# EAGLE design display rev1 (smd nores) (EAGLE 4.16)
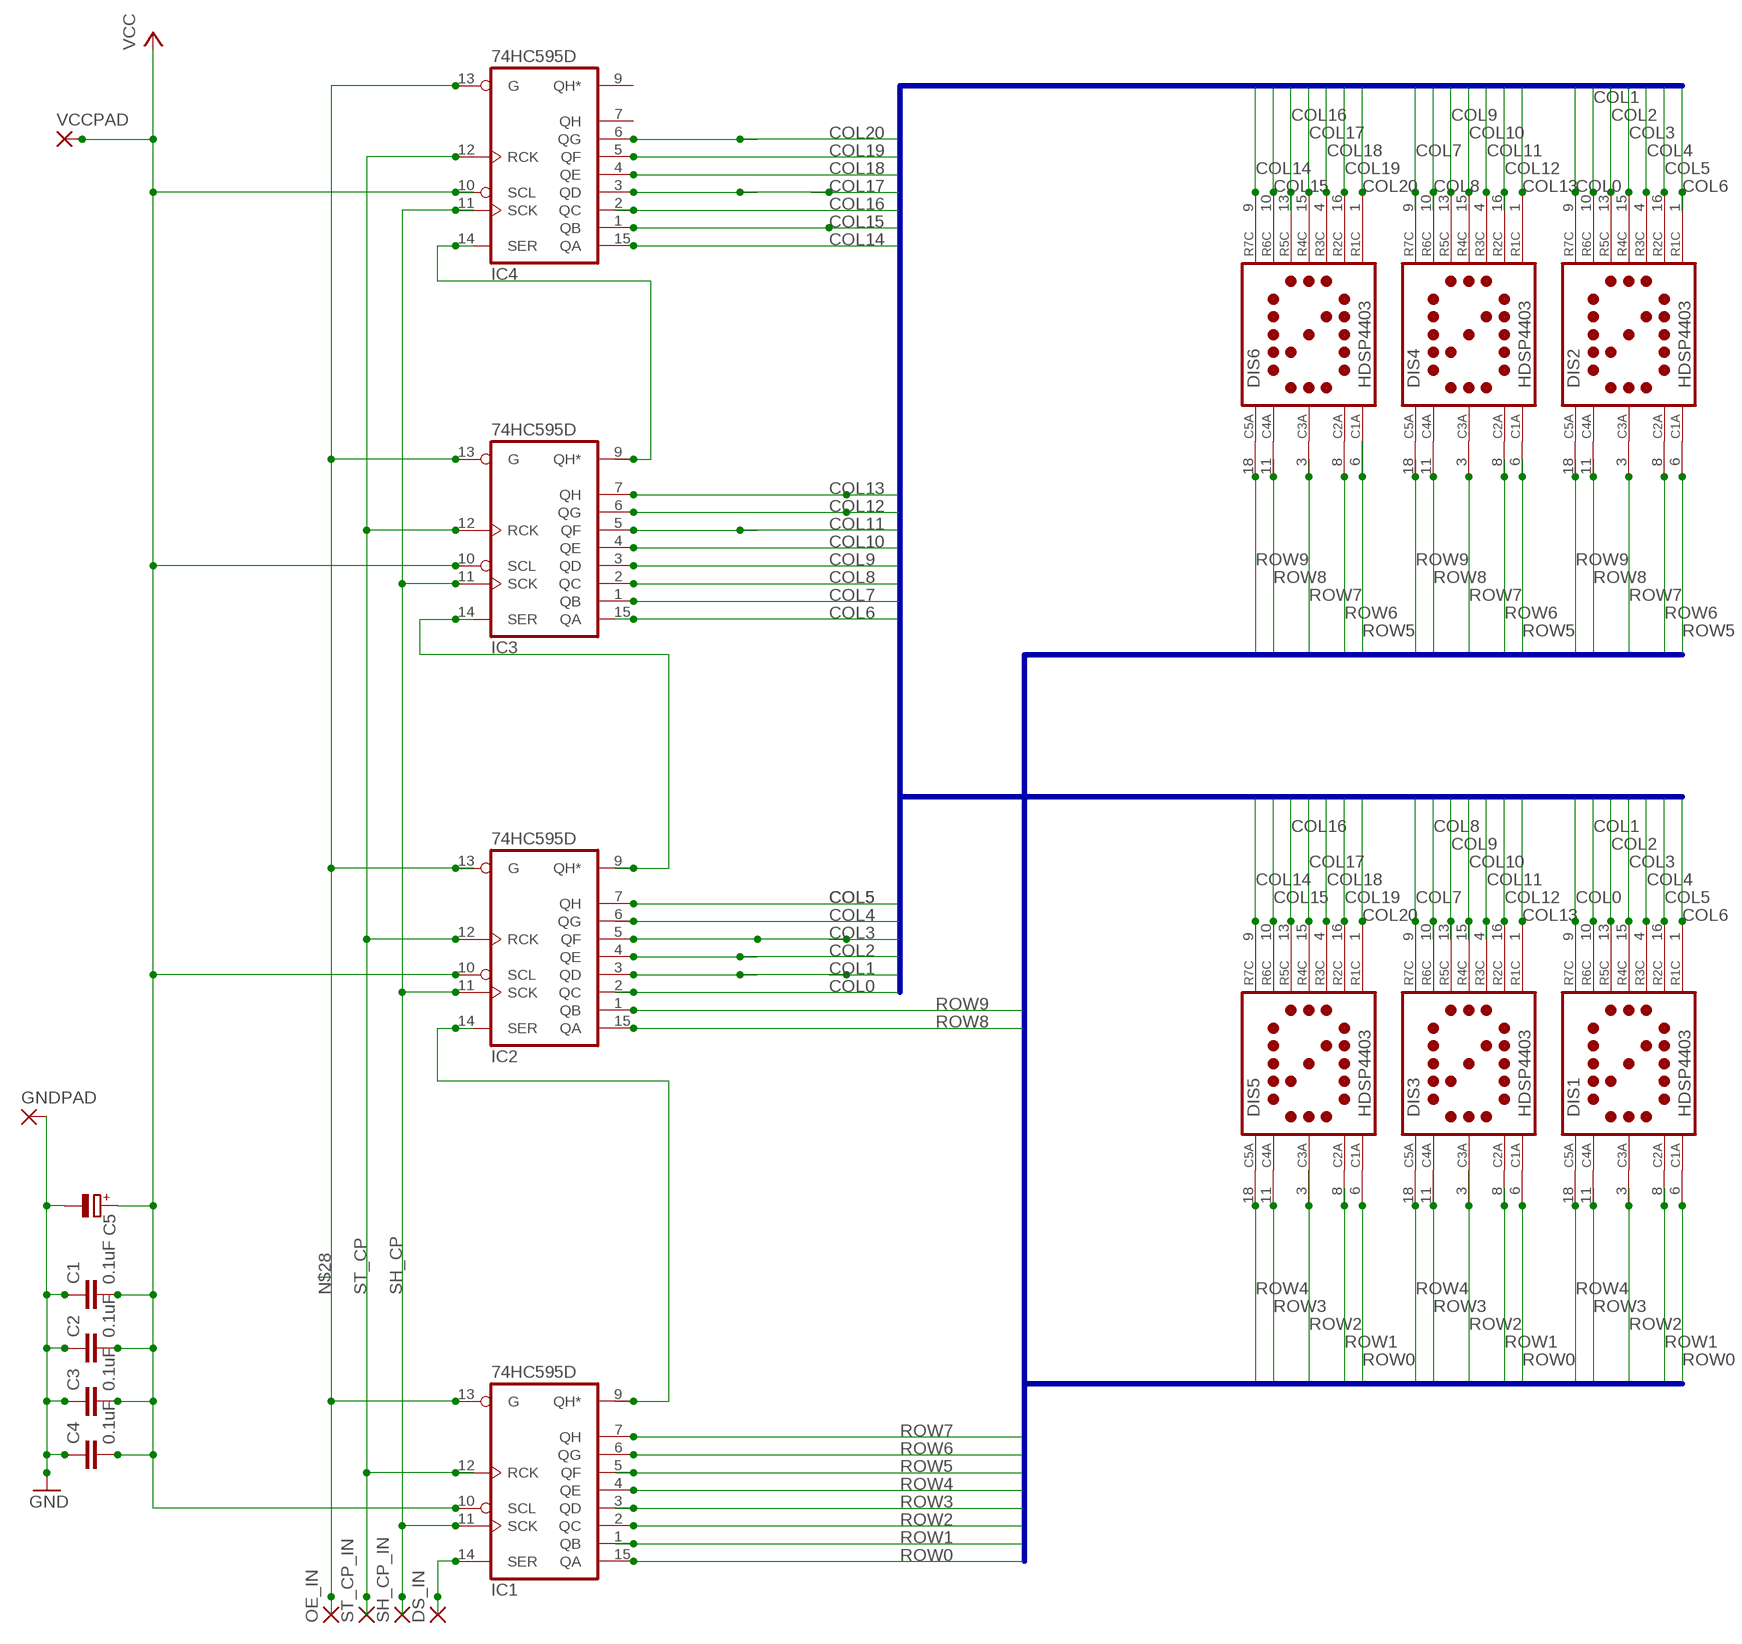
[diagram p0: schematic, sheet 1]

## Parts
C1  0.1uF  C-EUC0805K  [C0805K]
C2  0.1uF  C-EUC0805K  [C0805K]
C3  0.1uF  C-EUC0805K  [C0805K]
C4  0.1uF  C-EUC0805K  [C0805K]
C5  CPOL-EUA/3216-18W  [A/3216-18W]
DIS1  HDSP4403  [HDSP44]
DIS2  HDSP4403  [HDSP44]
DIS3  HDSP4403  [HDSP44]
DIS4  HDSP4403  [HDSP44]
DIS5  HDSP4403  [HDSP44]
DIS6  HDSP4403  [HDSP44]
DS_IN  2,15/1,0  [2,15/1,0]
GNDPAD  2,15/1,0  [2,15/1,0]
IC1  74HC595D  [SO16]
IC2  74HC595D  [SO16]
IC3  74HC595D  [SO16]
IC4  74HC595D  [SO16]
OE_IN  2,15/1,0  [2,15/1,0]
SH_CP_IN  2,15/1,0  [2,15/1,0]
ST_CP_IN  2,15/1,0  [2,15/1,0]
VCCPAD  2,15/1,0  [2,15/1,0]

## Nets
COL0: DIS1.9(R7C) DIS2.9(R7C) IC2.2(QC)
COL1: DIS1.10(R6C) DIS2.10(R6C) IC2.3(QD)
COL2: DIS1.13(R5C) DIS2.13(R5C) IC2.4(QE)
COL3: DIS1.15(R4C) DIS2.15(R4C) IC2.5(QF)
COL4: DIS1.4(R3C) DIS2.4(R3C) IC2.6(QG)
COL5: DIS1.16(R2C) DIS2.16(R2C) IC2.7(QH)
COL6: DIS1.1(R1C) DIS2.1(R1C) IC3.15(QA)
COL7: DIS3.9(R7C) DIS4.9(R7C) IC3.1(QB)
COL8: DIS3.10(R6C) DIS4.10(R6C) IC3.2(QC)
COL9: DIS3.13(R5C) DIS4.13(R5C) IC3.3(QD)
COL10: DIS3.15(R4C) DIS4.15(R4C) IC3.4(QE)
COL11: DIS3.4(R3C) DIS4.4(R3C) IC3.5(QF)
COL12: DIS3.16(R2C) DIS4.16(R2C) IC3.6(QG)
COL13: DIS3.1(R1C) DIS4.1(R1C) IC3.7(QH)
COL14: DIS5.9(R7C) DIS6.9(R7C) IC4.15(QA)
COL15: DIS5.10(R6C) DIS6.10(R6C) IC4.1(QB)
COL16: DIS5.13(R5C) DIS6.13(R5C) IC4.2(QC)
COL17: DIS5.15(R4C) DIS6.15(R4C) IC4.3(QD)
COL18: DIS5.4(R3C) DIS6.4(R3C) IC4.4(QE)
COL19: DIS5.16(R2C) DIS6.16(R2C) IC4.5(QF)
COL20: DIS5.1(R1C) DIS6.1(R1C) IC4.6(QG)
GND: C1.1 C2.1 C3.1 C4.1 C5.- GNDPAD.1(P)
N$22: IC1.9(QH*) IC2.14(SER)
N$23: IC2.9(QH*) IC3.14(SER)
N$24: IC3.9(QH*) IC4.14(SER)
N$28: IC1.13(G) IC2.13(G) IC3.13(G) IC4.13(G) OE_IN.1(P)
N$29: DS_IN.1(P) IC1.14(SER)
ROW0: DIS1.6(C1A) DIS3.6(C1A) DIS5.6(C1A) IC1.15(QA)
ROW1: DIS1.8(C2A) DIS3.8(C2A) DIS5.8(C2A) IC1.1(QB)
ROW2: DIS1.3(C3A) DIS3.3(C3A) DIS5.3(C3A) IC1.2(QC)
ROW3: DIS1.11(C4A) DIS3.11(C4A) DIS5.11(C4A) IC1.3(QD)
ROW4: DIS1.18(C5A) DIS3.18(C5A) DIS5.18(C5A) IC1.4(QE)
ROW5: DIS2.6(C1A) DIS4.6(C1A) DIS6.6(C1A) IC1.5(QF)
ROW6: DIS2.8(C2A) DIS4.8(C2A) DIS6.8(C2A) IC1.6(QG)
ROW7: DIS2.3(C3A) DIS4.3(C3A) DIS6.3(C3A) IC1.7(QH)
ROW8: DIS2.11(C4A) DIS4.11(C4A) DIS6.11(C4A) IC2.15(QA)
ROW9: DIS2.18(C5A) DIS4.18(C5A) DIS6.18(C5A) IC2.1(QB)
SH_CP: IC1.11(SCK) IC2.11(SCK) IC3.11(SCK) IC4.11(SCK) SH_CP_IN.1(P)
ST_CP: IC1.12(RCK) IC2.12(RCK) IC3.12(RCK) IC4.12(RCK) ST_CP_IN.1(P)
VCC: C1.2 C2.2 C3.2 C4.2 C5.+ IC1.10(SCL) IC2.10(SCL) IC3.10(SCL) IC4.10(SCL) VCCPAD.1(P)
Unconnected: IC4.7(QH) IC4.9(QH*)

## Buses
COL[0..20]
ROW[0..9]

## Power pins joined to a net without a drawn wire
GND: IC1.8(GND) IC2.8(GND) IC3.8(GND) IC4.8(GND)
VCC: IC1.16(VCC) IC2.16(VCC) IC3.16(VCC) IC4.16(VCC)

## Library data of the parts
C1-C4 = rcl:C-EU: CAPACITOR, European symbol
C5 = rcl:CPOL-EU: POLARIZED CAPACITOR, European symbol
DIS1-DIS6 = display-hp:HDSP4403: LED DISPLAY 1-character dot matrix without decimal point
DS_IN GNDPAD OE_IN SH_CP_IN ST_CP_IN VCCPAD = wirepad:2,15/1,0: THROUGH-HOLE PAD
IC1-IC4 = 74xx-eu:74*595: 8-bit SHIFT REGISTER, output latch

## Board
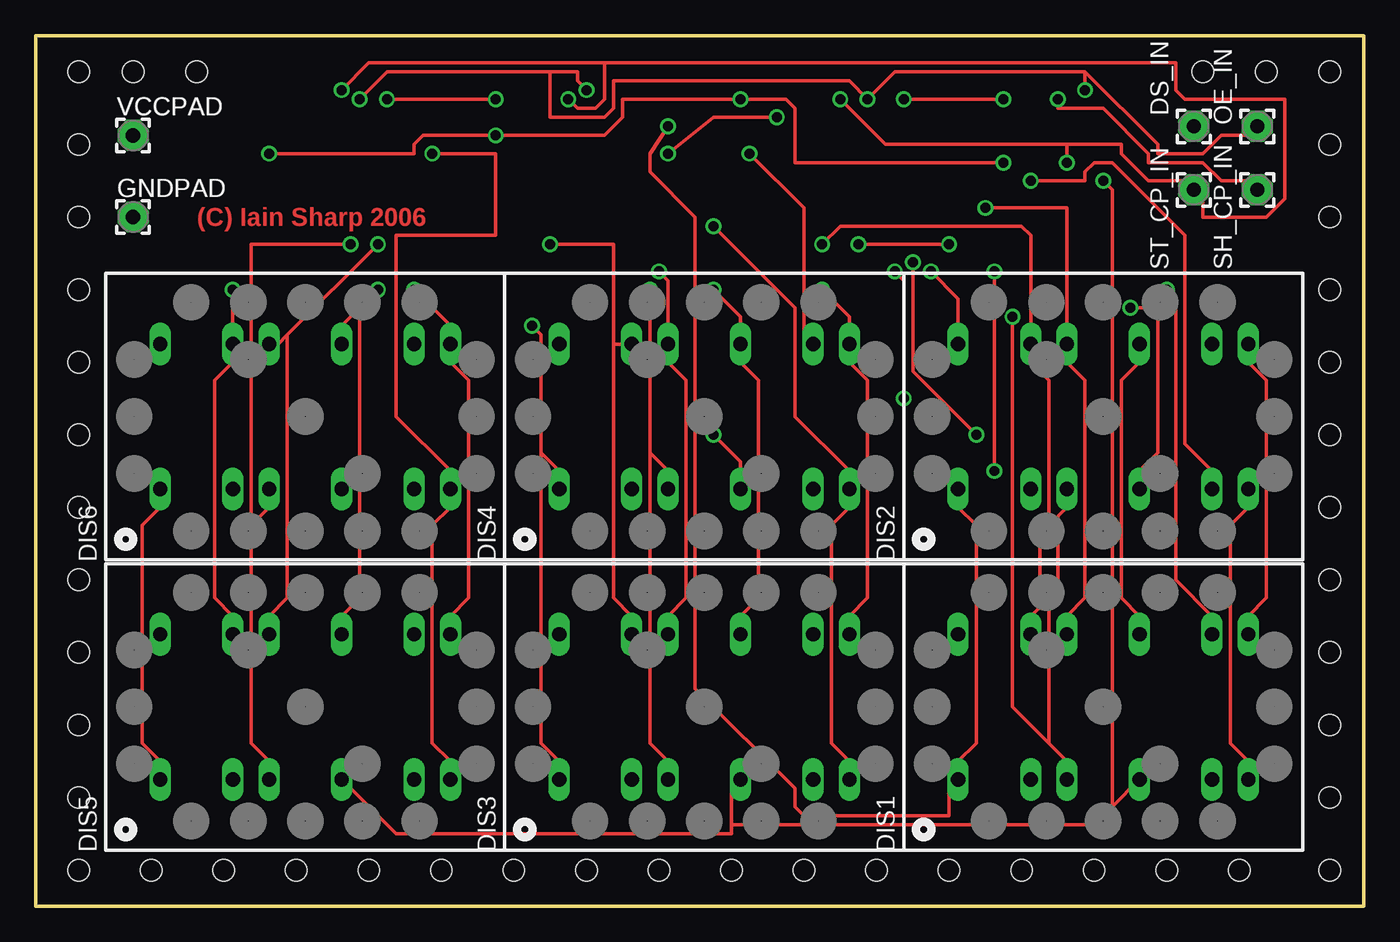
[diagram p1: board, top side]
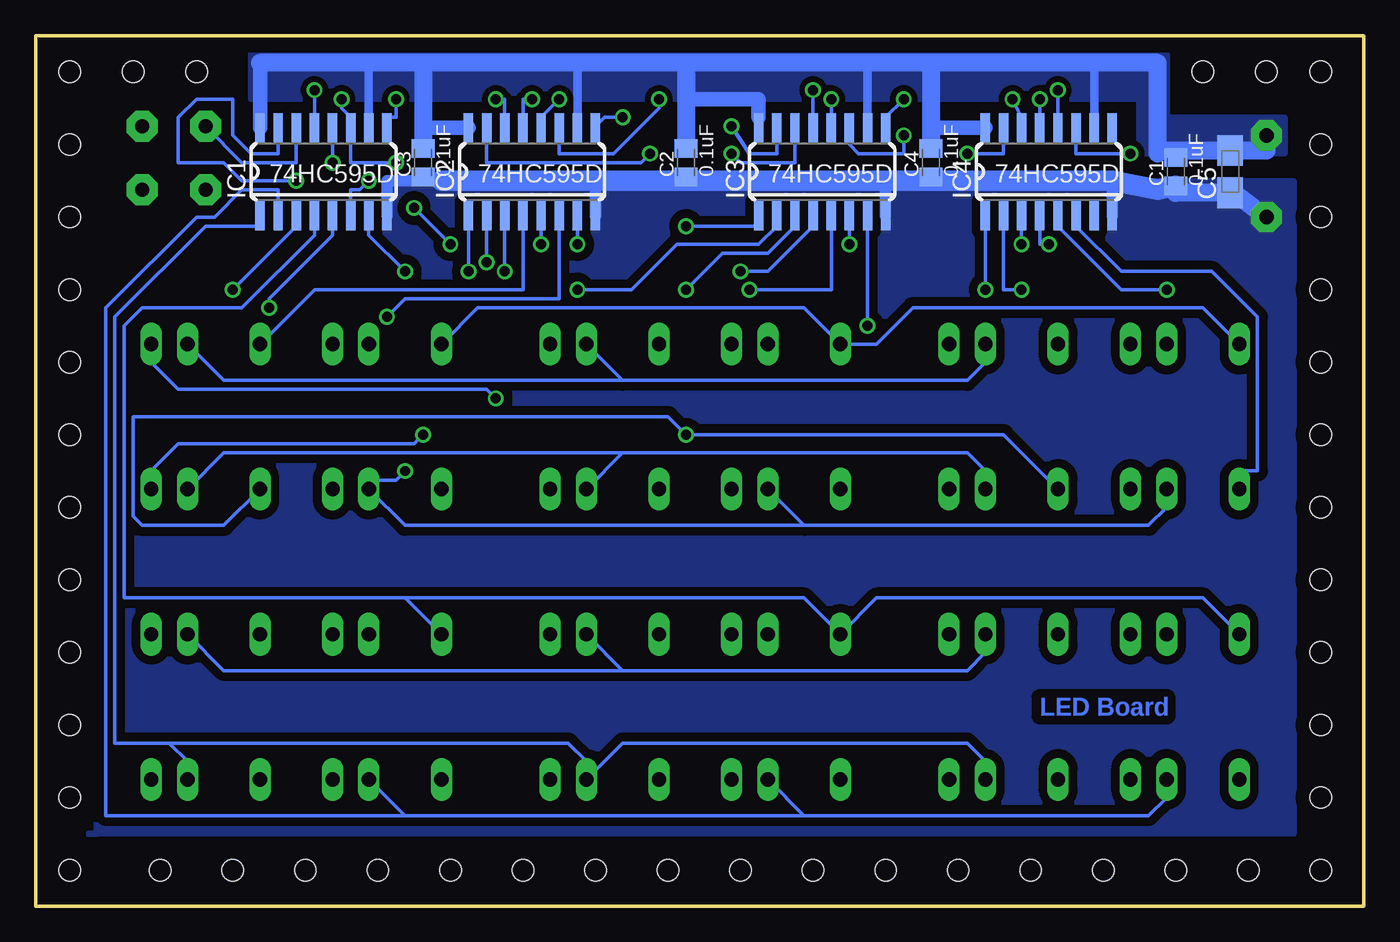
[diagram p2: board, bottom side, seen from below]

Size 93.02 x 60.95 mm. Coordinates in mm from the lower left corner, seen from the top.
Outline: 0,0 93.02,0 93.02,60.95 0,60.95 0,0
Copper layers (1*16): Top 0.035mm / dielectric 1.5mm / Bottom 0.035mm
Design rules "10mils with 0.7mm min drill 12mil clearence": minimum track width 10mil, minimum drill 0.7mm, track to track 12mil, track to pad 12mil, pad to pad 12mil, via to via 12mil, smd to smd 12mil, copper to edge 40mil, drill to drill 10mil, minimum pad ring 10mil, minimum via ring 8mil, stop-mask expansion 0mil, vias tented up to drill 0mil, thermal gap 10mil
Holes 1.5 mm at 3.01,58.41 3.01,53.34 3.01,48.26 6.82,58.41 11.26,58.41 90.64,58.41 90.64,53.34 3.01,2.54 8.09,2.54 13.17,2.54 3.01,7.62 3.01,12.7 3.01,43.18 3.01,38.09 3.01,33.02 3.01,27.94 3.01,22.86 3.01,17.78 18.25,2.54 23.33,2.54 28.41,2.54 33.49,2.54 38.57,2.54 43.65,2.54 48.73,2.54 53.81,2.54 58.89,2.54 63.97,2.54 69.05,2.54 74.13,2.54 79.21,2.54 84.29,2.54 90.64,2.54 90.64,7.62 90.64,12.7 90.64,17.78 90.64,22.86 90.64,27.94 90.64,33.02 90.64,38.09 90.64,43.18 90.64,48.26 86.2,58.41 81.75,58.41

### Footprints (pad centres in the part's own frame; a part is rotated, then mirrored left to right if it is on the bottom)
C0805K = smd 1.3 x 1.6: 1 -1,0; 2 1,0
A/3216-18W = smd 2.15 x 1.8: + 1.475,0; - -1.475,0
HDSP44 = drill 1 long: 1 -5.08,10.16; 3 -5.08,5.08; 4 -5.08,2.54; 6 -5.08,-2.54; 8 -5.08,-7.62; 9 -5.08,-10.16; 10 5.08,-10.16; 11 5.08,-7.62; 13 5.08,-2.54; 15 5.08,2.54; 16 5.08,5.08; 18 5.08,10.16
2,15/1,0 = drill 1 pad 2.159 octagon: 1 0,0
SO16 = smd 0.66 x 2.032: 1 -4.445,-3.073; 2 -3.175,-3.073; 3 -1.905,-3.073; 4 -0.635,-3.073; 5 0.635,-3.073; 6 1.905,-3.073; 7 3.175,-3.073; 8 4.445,-3.073; 9 4.445,3.073; 10 3.175,3.073; 11 1.905,3.073; 12 0.635,3.073; 13 -0.635,3.073; 14 -1.905,3.073; 15 -3.175,3.073; 16 -4.445,3.073

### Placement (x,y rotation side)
C1  13.17,51.43 90 bottom
C2  47.46,52.07 90 bottom
C3  65.88,52.07 90 bottom
C4  30.31,52.07 90 bottom
C5  9.36,51.43 90 bottom
DIS1  74.77,13.96 90 top
DIS2  74.77,34.29 90 top
DIS3  46.83,13.96 90 top
DIS4  46.83,34.29 90 top
DIS5  18.88,13.96 90 top
DIS6  18.88,34.29 90 top
DS_IN  81.12,54.61 0 top
GNDPAD  6.82,48.26 0 top
IC1  72.86,51.43 0 bottom
IC2  58.26,51.43 0 bottom
IC3  37.94,51.43 0 bottom
IC4  22.06,51.43 0 bottom
OE_IN  85.56,54.61 0 top
SH_CP_IN  85.56,50.16 0 top
ST_CP_IN  81.12,50.16 0 top
VCCPAD  6.82,53.97 0 top

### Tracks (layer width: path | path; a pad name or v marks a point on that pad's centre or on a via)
COL0  (via drill 0.7)
  Top 0.254: v61.43,45.08 61.43,37.46 v65.88,33.02 | DIS1.9 84.92,10.15 83.66,11.42 83.66,26.67 84.92,27.94 DIS2.9
  Bottom 0.254: v65.88,33.02 66.51,32.38 83.02,32.38 84.92,30.48 DIS2.9 | v61.43,45.08 IC2.2
COL1  (via drill 0.7)
  Top 0.254: DIS1.10 84.92,20.32 86.2,21.59 86.2,36.83 84.92,38.09 DIS2.10 | v60.16,44.45 60.8,43.81 v60.8,35.55
  Bottom 0.254: v60.16,44.45 IC2.3 | v60.8,35.55 61.43,36.19 83.02,36.19 84.92,38.09 DIS2.10
COL2
  Top 0.254: DIS1.13 77.31,20.32 76.03,21.59 76.03,36.83 77.31,38.09 DIS2.13
  Bottom 0.254: IC2.4 58.89,43.18 73.5,43.18 DIS2.13
COL3  (via drill 0.7)
  Top 0.254: v66.51,48.89 72.23,48.89 DIS2.15 72.23,38.09 73.5,36.83 73.5,21.59 72.23,20.32 DIS1.15 | v63.97,46.35 v57.62,46.35
  Bottom 0.254: v66.51,48.89 v63.97,46.35 | v57.62,46.35 IC2.5
COL4  (via drill 0.7)
  Top 0.254: v68.42,41.27 68.42,13.96 70.95,11.42 | 70.95,11.42 72.23,10.15 DIS1.4 | 70.95,11.42 70.95,20.95 71.59,21.59 71.59,27.3 72.23,27.94 DIS2.4
  Bottom 0.254: v68.42,41.27 67.14,42.54 56.35,42.54 IC2.6
COL5  (via drill 0.7)
  Top 0.254: v55.08,46.35 56.35,47.62 69.05,47.62 69.69,46.98 DIS2.16 69.69,38.09 70.95,36.83 70.95,27.3 70.32,26.67 70.32,20.95 69.69,20.32 DIS1.16
  Bottom 0.254: v55.08,46.35 IC2.7
COL6  (via drill 0.7)
  Top 0.254: v44.29,54.61 43.02,52.7 43.02,51.43 46.19,48.26 46.19,15.24 53.18,8.25 53.18,6.98 53.81,6.35 63.97,6.35 63.97,8.25 DIS1.1 64.61,10.15 65.88,11.42 65.88,26.67 64.61,27.94 DIS2.1
  Bottom 0.254: IC3.15 41.11,52.7 43.02,52.7 v44.29,54.61
COL7  (via drill 0.7)
  Top 0.254: DIS3.9 56.98,10.15 55.72,11.42 55.72,26.67 56.98,27.94 DIS4.9 56.98,30.48 53.18,34.29 53.18,41.91 v47.46,47.62
  Bottom 0.254: v47.46,47.62 42.38,47.62 IC3.1
COL8  (via drill 0.7)
  Top 0.254: DIS3.10 56.98,20.32 58.26,21.59 58.26,36.83 56.98,38.09 DIS4.10 56.98,41.27 v55.08,43.18
  Bottom 0.254: IC3.2 41.11,47.62 42.38,46.35 48.1,46.35 51.27,43.18 v55.08,43.18
COL9  (via drill 0.7)
  Top 0.254: v47.46,43.18 49.37,41.27 DIS4.13 49.37,38.09 50.64,36.83 50.64,21.59 49.37,20.32 DIS3.13
  Bottom 0.254: v47.46,43.18 44.92,45.72 41.75,45.72 39.84,47.62 IC3.3
COL10  (via drill 0.7)
  Top 0.254: v43.65,44.45 44.29,43.81 DIS4.15 44.29,38.09 45.55,36.83 45.55,21.59 44.29,20.32 DIS3.15
  Bottom 0.254: v43.65,44.45 41.75,44.45 38.57,47.62 IC3.4
COL11  (via drill 0.7)
  Top 0.254: 43.02,31.75 v43.02,43.18 | 43.02,31.75 44.29,30.48 DIS4.4 | 43.02,31.75 43.02,11.42 44.29,10.15 DIS3.4
  Bottom 0.254: v43.02,43.18 37.3,43.18 IC3.5
COL12  (via drill 0.7)
  Top 0.254: v36.03,46.35 40.48,46.35 40.48,39.37 | 40.48,39.37 40.48,21.59 41.75,20.32 DIS3.16 | 40.48,39.37 DIS4.16
  Bottom 0.254: v36.03,46.35 IC3.6
COL13  (via drill 0.7)
  Top 0.254: v34.76,40.63 35.4,40 35.4,31.75 | 35.4,31.75 36.67,30.48 DIS4.1 | 35.4,31.75 35.4,11.42 36.67,10.15 DIS3.1
  Bottom 0.254: v34.76,40.63 IC3.7
COL14  (via drill 0.7)
  Top 0.254: v27.77,52.7 32.22,52.7 32.22,46.98 25.23,46.98 25.23,34.29 29.04,30.48 DIS6.9 29.04,27.94 27.77,26.67 27.77,11.42 29.04,10.15 DIS5.9
  Bottom 0.254: v27.77,52.7 25.23,52.7 IC4.15
COL15  (via drill 0.7)
  Top 0.254: v26.5,43.18 29.04,40.63 DIS6.10 29.04,38.09 30.31,36.83 30.31,21.59 29.04,20.32 DIS5.10
  Bottom 0.254: v26.5,43.18 IC4.1
COL16  (via drill 0.7)
  Top 0.254: 22.7,41.91 21.43,40.63 DIS6.13 | 22.7,41.91 v23.96,43.18 | 22.7,41.91 22.7,21.59 21.43,20.32 DIS5.13
  Bottom 0.254: v23.96,43.18 25.23,43.18 IC4.2
COL17  (via drill 0.7)
  Top 0.254: 17.61,40 16.98,39.37 DIS6.15 | 17.61,40 v23.96,46.35 | 17.61,40 17.61,21.59 16.34,20.32 DIS5.15
  Bottom 0.254: v23.96,46.35 IC4.3
COL18  (via drill 0.7)
  Top 0.254: v22.06,46.35 15.07,46.35 15.07,26.67 | 15.07,26.67 15.07,11.42 16.34,10.15 DIS5.4 | 15.07,26.67 16.34,27.94 DIS6.4
  Bottom 0.254: v22.06,46.35 22.7,46.35 IC4.4
COL19  (via drill 0.7)
  Top 0.254: v13.8,43.18 DIS6.16 13.8,38.09 12.54,36.83 12.54,21.59 13.8,20.32 DIS5.16
  Bottom 0.254: v13.8,43.18 16.98,43.18 21.43,47.62 IC4.5
COL20
  Top 0.254: DIS5.1 8.72,10.15 7.46,11.42 7.46,26.67 8.72,27.94 DIS6.1
  Bottom 0.254: IC4.6 20.15,47.62 16.98,44.45 10.63,44.45 7.46,41.27 7.46,30.48 8.72,30.48 DIS6.1
GND
  Bottom 0.61: IC1.8 68.42,47.62
  Bottom 0.813: 17.61,50.8 IC4.8 | 33.49,50.8 IC3.8 | 53.81,50.8 IC2.8 | IC1.8 68.42,50.8 64.61,50.8
  Bottom 1.016: 30.31,50.8 C4.1 | 47.46,50.8 C2.1 | 64.61,50.8 C3.1
  Bottom 1.27: GNDPAD.1 9.36,50.16 C5.- 13.17,49.95 C1.1
  Bottom 1.422: C1.1 14.44,50.16 17.61,50.8 30.31,50.8 33.49,50.8 47.46,50.8 53.81,50.8 64.61,50.8
  pour Bottom (isolate 0.61, no thermals): 4.92,50.8 4.92,5.07 89.37,5.07 88.73,5.07 88.73,50.8
N$22  (via drill 0.7)
  Top 0.254: v60.8,56.51 v67.78,56.51
  Bottom 0.254: v60.8,56.51 60.16,56.51 IC2.14 | v67.78,56.51 67.78,55.24 68.42,55.24 IC1.9
N$23  (via drill 0.7)
  Top 0.254: v44.29,52.7 47.46,55.24 v51.91,55.24
  Bottom 0.254: IC3.14 39.84,52.07 43.65,52.07 v44.29,52.7 | 53.81,53.97 IC2.9 53.81,54.61 53.18,55.24 v51.91,55.24
N$24  (via drill 0.7)
  Top 0.254: v24.6,56.51 v32.22,56.51
  Bottom 0.254: v24.6,56.51 23.96,55.24 IC4.14 | v32.22,56.51 33.49,55.24 IC3.9
N$28  (via drill 0.7)
  Top 0.254: v22.7,56.51 24.6,58.41 36.03,58.41 | 36.03,58.41 37.94,58.41 37.94,57.78 v38.57,57.15 | 36.03,58.41 36.03,55.24 39.84,55.24 40.48,55.88 40.48,57.78 56.98,57.78 v58.26,56.51 60.16,58.41 73.5,58.41 | 73.5,58.41 v73.5,57.15 | 73.5,58.41 78.58,53.34 78.58,52.7 81.75,52.7 83.02,53.97 84.92,53.97 OE_IN.1
  Bottom 0.254: IC4.13 v22.7,56.51 | v38.57,57.15 IC3.13 | v58.26,56.51 58.89,56.51 IC2.13 | v73.5,57.15 IC1.13
N$29
  Bottom 0.254: IC1.14 74.77,52.07 78.58,52.07 DS_IN.1
ROW0  (via drill 0.7)
  Top 0.254: 48.73,5.71 48.73,8.25 DIS3.6 | 48.73,5.71 48.73,5.07 25.23,5.07 DIS5.6 | 48.73,5.71 74.13,5.71 75.4,6.98 | 75.4,6.98 DIS1.6 | v74.77,50.8 75.4,50.16 75.4,6.98
  Bottom 0.254: v74.77,50.8 78.58,50.8 79.84,52.07 83.02,52.07 83.02,55.24 81.75,56.51 79.21,56.51 79.21,53.97 77.94,52.7 76.03,52.7 IC1.15
ROW1
  Bottom 0.254: IC1.1 77.31,47.62 81.12,47.62 87.47,41.27 87.47,11.42 83.66,11.42 | DIS5.8 26.5,10.15 27.77,11.42 51.91,11.42 DIS3.8 54.45,10.15 55.72,11.42 83.66,11.42 | 83.66,11.42 82.39,10.15 DIS1.8
ROW2
  Bottom 0.254: 39.21,6.35 15.07,6.35 13.8,7.62 DIS5.3 | 39.21,6.35 DIS3.3 | 39.21,6.35 67.14,6.35 | 67.14,6.35 DIS1.3 | 67.14,6.35 88.1,6.35 88.1,41.91 81.75,48.26 80.48,48.26 78.58,50.16 76.03,50.16 IC1.2
ROW3  (via drill 0.7)
  Top 0.254: v79.21,43.18 79.84,42.54 79.84,22.86 82.39,20.32 DIS1.11
  Bottom 0.254: 51.91,16.51 27.77,16.51 26.5,17.78 DIS5.11 | 51.91,16.51 DIS3.11 | 51.91,16.51 79.84,16.51 DIS1.11 | v79.21,43.18 74.77,47.62 IC1.3
ROW4
  Bottom 0.254: DIS5.18 11.26,21.59 34.12,21.59 DIS3.18 39.21,21.59 67.14,21.59 | 67.14,21.59 86.83,21.59 86.83,40.63 85.56,41.91 78.58,41.91 73.5,46.98 IC1.4 | 67.14,21.59 DIS1.18
ROW5  (via drill 0.7)
  Top 0.254: v47.46,33.02 49.37,31.11 DIS4.6 | v76.67,41.91 78.58,41.91 78.58,31.75 77.31,30.48 DIS2.6
  Bottom 0.254: DIS6.6 25.23,33.02 v47.46,33.02 48.73,34.29 86.2,34.29 86.2,27.3 85.56,26.67 79.84,26.67 DIS2.6 | v76.67,41.91 76.67,42.54 72.23,46.98 IC1.5
ROW6  (via drill 0.7)
  Top 0.254: DIS2.8 82.39,30.48 80.48,32.38 80.48,46.98 75.4,52.07 74.13,52.07 73.5,51.43 73.5,50.8 v69.69,50.8
  Bottom 0.254: 51.91,31.75 27.77,31.75 26.5,30.48 DIS6.8 | 51.91,31.75 DIS4.8 | 51.91,31.75 79.84,31.75 DIS2.8 | v69.69,50.8 70.32,50.16 70.95,50.16 IC1.6
ROW7  (via drill 0.7)
  Top 0.254: v67.14,30.48 v67.14,44.45
  Bottom 0.254: v67.14,44.45 69.69,46.98 IC1.7 | 39.21,26.67 15.07,26.67 13.8,27.94 DIS6.3 | 39.21,26.67 DIS4.3 | 39.21,26.67 67.14,26.67 DIS2.3 69.05,29.84 67.78,29.84 v67.14,30.48
ROW8  (via drill 0.7)
  Top 0.254: v50,52.7 53.81,48.89 53.81,40 DIS4.11
  Bottom 0.254: v50,52.7 50.64,52.07 61.43,52.07 IC2.15 | 51.91,36.83 27.77,36.83 26.5,38.09 DIS6.11 | 51.91,36.83 DIS4.11 | 51.91,36.83 79.84,36.83 DIS2.11
ROW9  (via drill 0.7)
  Top 0.254: v62.7,44.45 64.61,42.54 DIS2.18
  Bottom 0.254: v62.7,44.45 IC2.1 | DIS6.18 11.26,41.91 31.58,41.91 34.12,39.37 DIS4.18 39.21,41.91 62.07,41.91 DIS2.18
SH_CP  (via drill 0.7)
  Top 0.254: v16.34,52.7 26.5,52.7 26.5,53.34 27.14,53.97 v32.22,53.97 39.84,53.97 41.11,55.24 41.11,56.51 v49.37,56.51 52.54,56.51 53.18,55.88 53.18,52.07 v67.78,52.07 | v71.59,56.51 71.59,55.88 74.77,55.88 77.94,52.7 77.94,52.07 81.75,52.07 83.02,50.8 84.92,50.8 SH_CP_IN.1
  Bottom 0.254: IC1.11 70.95,54.61 | v16.34,52.7 20.15,52.7 IC4.11 | v32.22,53.97 32.22,52.7 35.4,52.7 36.03,53.34 IC3.11 | v49.37,56.51 49.37,55.88 52.54,52.7 56.35,52.7 IC2.11 | v67.78,52.07 70.95,52.07 IC1.11 | v71.59,56.51 71.59,55.88 70.95,55.24 IC1.11
ST_CP  (via drill 0.7)
  Top 0.254: v21.43,57.15 23.33,59.05 39.84,59.05 | v37.3,56.51 37.94,55.88 39.21,55.88 39.84,56.51 39.84,59.05 | v56.35,56.51 59.53,53.34 72.23,53.34 | 72.23,53.34 76.03,53.34 76.03,52.7 77.94,50.8 80.48,50.8 ST_CP_IN.1 81.75,49.52 81.75,48.26 86.2,48.26 87.47,49.52 87.47,56.51 80.48,56.51 79.84,57.15 79.84,59.05 39.84,59.05 | 72.23,53.34 v72.23,52.07
  Bottom 0.254: IC4.12 v21.43,57.15 | v37.3,56.51 IC3.12 | v56.35,56.51 57.62,55.24 IC2.12 | v72.23,52.07 IC1.12
VCC
  Bottom 0.254: 18.88,55.24 IC4.10 | 55.08,55.24 IC2.10 | 42.38,55.24 IC3.16 | IC2.16 62.7,55.24 | 14.44,52.7 C1.2
  Bottom 0.61: 18.88,59.05 18.88,55.24 | 34.76,59.05 IC3.10 | 55.08,59.05 55.08,55.24 | 69.69,59.05 IC1.10
  Bottom 1.016: 77.31,59.05 IC1.16 | IC4.16 30.31,54.5 30.31,54.61 | 42.38,55.24 42.38,56.51 47.46,56.51 | IC2.16 65.88,54.5 65.88,54.61
  Bottom 1.27: 30.31,59.05 18.88,59.05 14.44,59.05 14.44,52.7 14.44,52.91 C5.+ 6.82,52.91 VCCPAD.1 | 30.31,59.05 34.76,59.05 47.46,59.05 | 47.46,59.05 47.46,56.51 C2.2 | 47.46,59.05 55.08,59.05 65.88,59.05 | 65.88,59.05 69.69,59.05 77.31,59.05 | 30.31,59.05 30.31,54.61 C4.2 | 65.88,59.05 65.88,54.61 C3.2
  pour Bottom (isolate 0.406, no thermals): 5.55,52.7 15.71,52.7 15.71,56.51 77.94,56.51 77.94,59.69 13.8,59.69 13.8,55.24 5.55,55.24

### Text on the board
Top: (C) Iain Sharp 2006
Bottom: LED Board
tNames: VCCPAD | GNDPAD
bNames: 0.1uF | C1 | 74HC595D | 0.1uF | C4 | 74HC595D | 0.1uF | C2 | 74HC595D | 0.1uF | C3 | 74HC595D | C5 | IC4 | IC3 | IC2 | IC1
